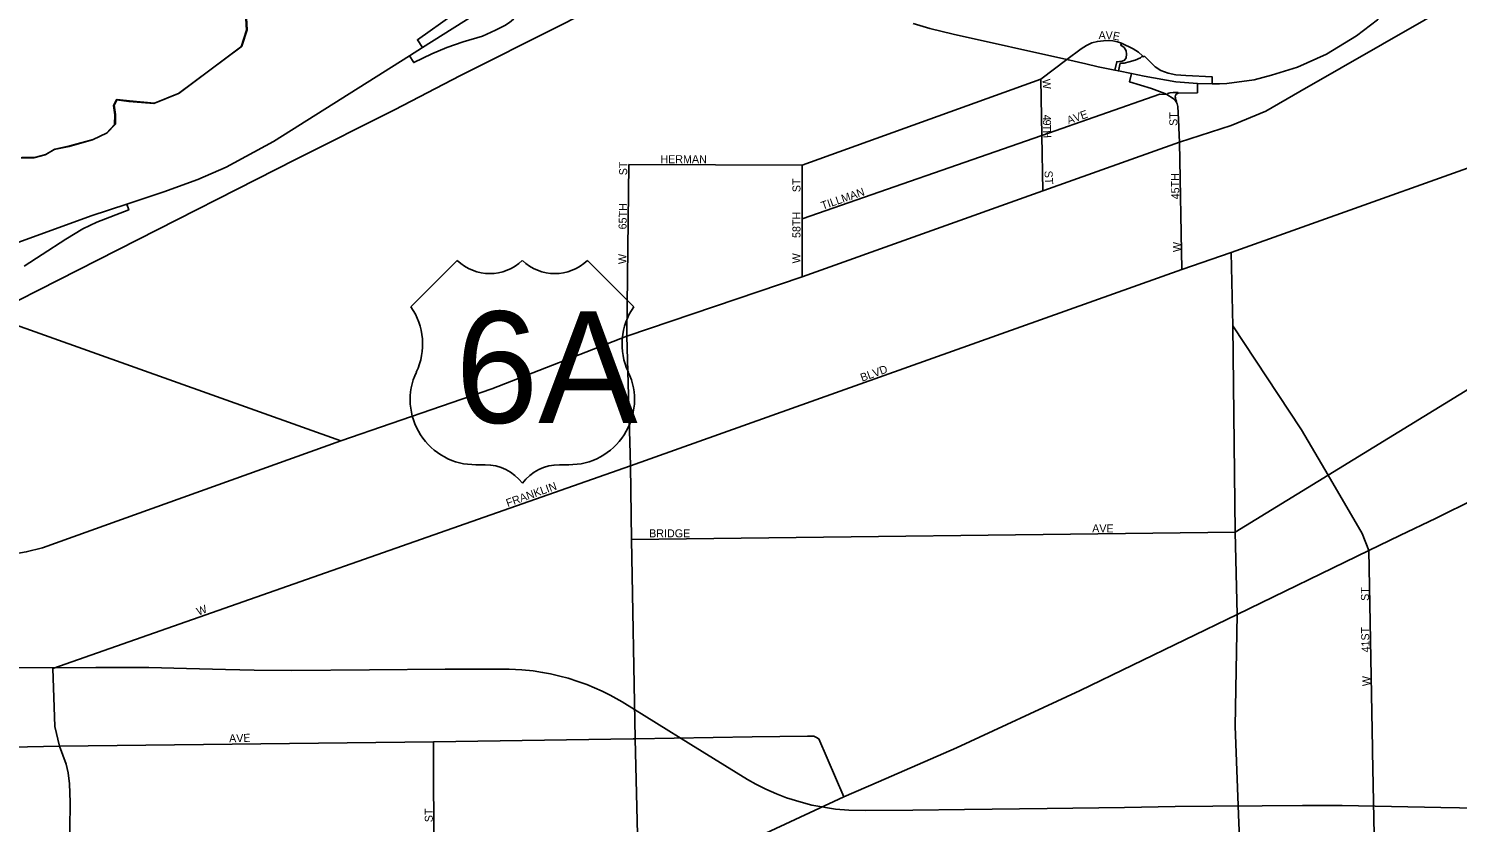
# Model space of a CAD drawing. Extents: x -561 to 1170, y 0 to 846.
# Drawn here: x 204.98 to 229.07, y 265.44 to 278.82 of the extents above; entities that cross this region are included whole.
import ezdxf

# ---------------------------------------------------------------- set-up
doc = ezdxf.new("R2010")
doc.units = 0
for name, color, linetype in [('GM_X_City_Street', 7, 'Continuous'), ('GM_X_City_Street_Text', 7, 'Continuous'), ('GM_X_County', 7, 'Continuous'), ('GM_X_Interchange_Ramps', 7, 'Continuous'), ('GM_X_Major_Lake', 7, 'Continuous'), ('GM_X_Rail_Line', 7, 'Continuous'), ('GM_X_State_Route', 7, 'Continuous'), ('GM_X_US_Location', 7, 'Continuous'), ('GM_X_US_Route', 7, 'Continuous'), ('GM_X_US_Shield', 7, 'Continuous')]:
    doc.layers.add(name, color=color, linetype=linetype)

msp = doc.modelspace()

# ---------------------------------------------------------------- linework, layer by layer
at = {"layer": 'GM_X_City_Street'}
for points in [[(223.779, 278.339), (223.76, 278.361), (223.693, 278.421), (223.604, 278.482), (223.409, 278.575), (223.337, 278.599), (223.262, 278.613), (223.18, 278.618), (223.101, 278.616), (223.002, 278.605), (222.904, 278.58), (222.816, 278.537), (222.728, 278.481), (222.483, 278.301), (222.047, 277.966)], [(222.047, 277.966), (218.021, 276.52), (215.101, 276.529)], [(222.078, 276.083), (222.063, 277.021), (222.047, 277.966)], [(222.063, 277.021), (224.053, 277.714), (224.171, 277.71)], [(224.38, 277.026), (224.367, 277.286), (224.357, 277.51), (224.347, 277.551), (224.329, 277.588), (224.308, 277.619), (224.281, 277.645), (224.171, 277.71)], [(225.254, 275.047), (231.085, 277.124)], [(218.02, 275.613), (222.063, 277.021)], [(224.424, 274.758), (224.386, 276.909), (224.38, 277.026)], [(215.065, 273.687), (215.101, 276.529)], [(218.019, 274.635), (218.02, 275.613), (218.021, 276.52)], [(215.146, 270.207), (225.325, 270.329), (226.891, 271.29), (229.871, 273.119), (233.973, 275.638)], [(224.424, 274.758), (225.254, 275.047)], [(225.391, 263.238), (225.407, 263.396), (225.406, 264.488), (225.406, 264.937), (225.387, 265.424), (225.324, 267.059), (225.36, 268.941), (225.325, 270.329), (225.287, 273.807), (225.254, 275.047)], [(205.386, 268.03), (215.124, 271.45), (224.424, 274.758)], [(202.964, 274.313), (203.134, 274.279), (204.598, 273.883), (210.242, 271.869)], [(226.43, 272.073), (225.287, 273.807)], [(215.264, 253.931), (215.357, 259.417), (215.312, 261.771), (215.265, 264.31), (215.207, 266.848), (215.146, 270.207), (215.124, 271.45), (215.064, 273.633), (215.065, 273.687)], [(227.581, 270.023), (227.466, 270.311), (226.891, 271.29), (226.441, 272.057), (226.43, 272.073)], [(227.641, 266.634), (227.64, 266.687), (227.581, 270.023)], [(205.746, 260.149), (205.705, 260.244), (205.65, 260.443), (205.65, 263.478), (205.678, 265.777), (205.665, 266.089), (205.643, 266.276), (205.612, 266.422), (205.496, 266.721), (205.42, 267.054), (205.386, 268.03)], [(191.454, 266.438), (197.428, 266.555), (205.496, 266.721), (211.806, 266.796), (215.172, 266.847)], [(211.817, 262.781), (211.806, 266.796)], [(215.172, 266.847), (215.207, 266.848), (217.181, 266.878), (218.112, 266.893), (218.218, 266.89), (218.253, 266.873)], [(218.253, 266.873), (218.301, 266.849), (218.724, 265.868)], [(227.739, 261.212), (227.721, 262.466), (227.689, 264.133), (227.68, 264.601), (227.668, 265.222), (227.641, 266.634)]]:
    msp.add_lwpolyline(points, dxfattribs=at)
at = {"layer": 'GM_X_County'}
msp.add_lwpolyline([(204.849, 276.641), (205.066, 276.642), (205.255, 276.692), (205.406, 276.78), (205.66, 276.835), (206.055, 276.946), (206.287, 277.056), (206.427, 277.203), (206.431, 277.365), (206.409, 277.522), (206.457, 277.62), (206.668, 277.594), (207.085, 277.559), (207.501, 277.724), (208.558, 278.515), (208.648, 278.792), (208.624, 279.285)], dxfattribs=at)
at = {"layer": 'GM_X_Interchange_Ramps'}
for points in [[(212.811, 280.059), (212.78, 279.98), (212.674, 279.722), (212.628, 279.622), (212.571, 279.531), (212.482, 279.411), (212.352, 279.268), (212.236, 279.149), (212.137, 279.056), (211.534, 278.634), (211.617, 278.501)], [(211.4, 278.364), (211.471, 278.248), (211.776, 278.396), (212.029, 278.5), (212.305, 278.597), (212.628, 278.696), (212.851, 278.793), (213.006, 278.875), (213.084, 278.923), (213.151, 278.979), (213.267, 279.103), (213.336, 279.199), (213.357, 279.254)], [(223.409, 278.575), (223.394, 278.54), (223.45, 278.502), (223.488, 278.446), (223.492, 278.391), (223.488, 278.327), (223.458, 278.288), (223.42, 278.271), (223.326, 278.263), (223.297, 278.12)], [(223.76, 278.361), (223.727, 278.327), (223.637, 278.288), (223.535, 278.263), (223.454, 278.237), (223.382, 278.237), (223.355, 278.108)], [(224.936, 277.889), (224.938, 278.007), (224.49, 278.032), (224.324, 278.041), (224.196, 278.071), (224.072, 278.113), (223.974, 278.177), (223.797, 278.354), (223.779, 278.339)], [(223.575, 278.063), (223.544, 277.921), (223.914, 277.809), (224.094, 277.745), (224.139, 277.725), (224.171, 277.71)], [(224.329, 277.588), (224.337, 277.593), (224.324, 277.619), (224.315, 277.653), (224.313, 277.671), (224.316, 277.692), (224.329, 277.714), (224.35, 277.727), (224.362, 277.731), (224.687, 277.738), (224.69, 277.893)], [(224.171, 277.71), (224.19, 277.726), (224.206, 277.734), (224.226, 277.738), (224.278, 277.741), (224.362, 277.742), (224.362, 277.731)], [(204.902, 274.818), (205.207, 275.012), (205.601, 275.272), (205.891, 275.443), (206.129, 275.555), (206.664, 275.763), (206.631, 275.861)]]:
    msp.add_lwpolyline(points, dxfattribs=at)
at = {"layer": 'GM_X_Major_Lake'}
msp.add_lwpolyline([(204.861, 276.648), (205.077, 276.649), (205.267, 276.699), (205.418, 276.787), (205.672, 276.842), (206.067, 276.953), (206.299, 277.063), (206.439, 277.21), (206.443, 277.372), (206.42, 277.529), (206.469, 277.627), (206.68, 277.601), (207.097, 277.566), (207.513, 277.731), (208.57, 278.522), (208.66, 278.799), (208.635, 279.292)], dxfattribs=at)
at = {"layer": 'GM_X_Rail_Line'}
for points in [[(197.077, 270.293), (200.273, 271.928), (203.47, 273.56), (209.487, 276.62), (211.146, 277.453), (212.262, 278.028), (213.918, 278.864), (215.28, 279.559), (215.714, 279.774), (217.261, 280.569), (217.693, 280.79), (218.131, 281.017), (218.428, 281.186), (218.73, 281.358), (219.028, 281.542), (219.677, 281.985), (220.829, 282.791), (222.601, 284.04), (224.719, 285.505)], [(204.621, 268.042), (206.109, 268.052), (207.001, 268.048), (207.639, 268.034), (208.296, 268.015), (208.782, 268.005), (209.417, 268), (210.724, 268.011), (211.999, 268.022), (213.078, 268.022), (213.292, 268.013), (213.486, 267.993), (213.645, 267.966), (213.78, 267.941), (213.932, 267.904), (214.073, 267.869), (214.237, 267.816), (214.388, 267.762), (214.522, 267.707), (214.647, 267.65), (214.785, 267.582), (214.984, 267.469), (216.144, 266.749), (217.098, 266.164), (217.241, 266.085), (217.409, 265.998), (217.59, 265.92), (217.759, 265.853), (218.002, 265.777), (218.187, 265.731)], [(218.187, 265.731), (218.586, 265.663), (218.809, 265.645), (219.082, 265.639), (219.888, 265.645), (220.76, 265.653), (222.156, 265.673), (223.459, 265.688), (224.313, 265.705), (224.945, 265.711), (225.782, 265.719), (226.457, 265.725), (227.127, 265.722), (228.793, 265.688), (229.737, 265.67)]]:
    msp.add_lwpolyline(points, dxfattribs=at)
at = {"layer": 'GM_X_State_Route'}
for points in [[(219.308, 266.123), (220.622, 266.696), (222.711, 267.664), (225.36, 268.941), (227.581, 270.023), (228.102, 270.274), (228.711, 270.57), (229.373, 270.892), (230.356, 271.362), (230.602, 271.478), (231.174, 271.751), (231.804, 272.052), (232.359, 272.331), (232.843, 272.579), (233.092, 272.697), (233.394, 272.883), (233.645, 273.045), (234.315, 273.462), (235.012, 273.892)], [(207.911, 260.99), (207.941, 261.004), (209.132, 261.538), (211.647, 262.696), (211.817, 262.781), (215.265, 264.31), (215.836, 264.564), (216.586, 264.876), (218.724, 265.868), (219.308, 266.123)]]:
    msp.add_lwpolyline(points, dxfattribs=at)
at = {"layer": 'GM_X_US_Route'}
for points in [[(225.057, 277.892), (225.183, 277.895), (225.642, 277.958), (225.934, 278.034), (226.376, 278.169), (226.864, 278.391), (227.369, 278.698), (227.724, 278.967), (227.961, 279.211), (228.181, 279.445), (228.397, 279.656)], [(204.565, 275.13), (206.031, 275.662), (206.631, 275.861), (207.254, 276.068), (207.832, 276.277), (208.308, 276.482), (209.104, 276.916), (211.4, 278.364), (211.617, 278.501), (213.211, 279.506)], [(222.099, 276.091), (224.386, 276.909), (225.255, 277.189), (225.84, 277.429), (226.412, 277.763), (229.201, 279.362), (229.299, 279.418)], [(219.894, 278.907), (220.177, 278.82), (220.569, 278.726), (222.483, 278.301), (222.808, 278.225)], [(222.808, 278.225), (223.015, 278.177), (223.297, 278.12), (223.355, 278.108), (223.575, 278.063), (223.788, 278.02), (224.324, 277.922), (224.69, 277.893), (224.936, 277.889), (225.057, 277.892)], [(210.242, 271.869), (212.786, 272.747), (215.064, 273.633), (218.019, 274.635), (222.078, 276.083), (222.099, 276.091)], [(200.373, 269.475), (200.373, 269.475), (204.715, 269.959), (204.935, 269.997), (205.21, 270.066), (210.242, 271.869)]]:
    msp.add_lwpolyline(points, dxfattribs=at)
at = {"layer": 'GM_X_US_Shield'}
for p, q in [((212.206, 274.914), (211.423, 274.131)), ((215.182, 274.131), (214.399, 274.914)), ((212.519, 271.468), (212.676, 271.468)), ((213.929, 271.468), (214.085, 271.468))]:
    msp.add_line(p, q, dxfattribs=at)
for centre, radius, start, end in [((212.754, 275.473), 0.783, 225.573, 314.427), ((213.851, 275.473), 0.783, 225.573, 314.427), ((210.525, 273.502), 1.096, 334.5471, 35.0009), ((216.08, 273.502), 1.096, 144.9991, 205.4529), ((212.507, 272.564), 1.096, 154.8319, 270.6383), ((214.098, 272.564), 1.096, 269.3617, 25.1681), ((212.676, 270.685), 0.783, 36.8699, 90), ((213.929, 270.685), 0.783, 90, 143.1301)]:
    msp.add_arc(centre, radius, start, end, dxfattribs=at)

# ---------------------------------------------------------------- texts
at = {"layer": 'GM_X_City_Street_Text'}
for s, rotation, p in [('A', 359.5191, (223.02, 278.643)), ('V', 359.1038, (223.138, 278.642)), ('E', 349.0598, (223.251, 278.64)), ('W', 274.7606, (222.071, 277.966)), ('4', 270.0625, (222.083, 277.37)), ('AVE', 19.6509, (222.513, 277.204)), ('ST', 90, (224.349, 277.18)), ('9', 270.0312, (222.083, 277.287)), ('T', 270.0668, (222.083, 277.203)), ('H', 271.625, (222.084, 277.104)), ('HERMAN', 0, (215.631, 276.552)), ('ST', 90, (215.071, 276.348)), ('ST', 273.5882, (222.107, 276.421)), ('ST', 90, (217.993, 276.063)), ('45TH', 91.3684, (224.385, 275.944)), ('TILLMAN', 19.0253, (218.367, 275.766)), ('65TH', 88.6369, (215.059, 275.434)), ('58TH', 90, (217.993, 275.291)), ('W', 90, (224.409, 275.053)), ('W', 90, (215.059, 274.851)), ('W', 90, (217.993, 274.863)), ('BLVD', 19.8563, (219.032, 272.867)), ('FRANKLIN', 19.799, (213.056, 270.753)), ('BRIDGE', 0, (215.441, 270.244)), ('AVE', 0, (222.913, 270.327)), ('ST', 90, (227.58, 269.173)), ('W', 21.0409, (207.84, 268.923)), ('41ST', 91.4313, (227.592, 268.305)), ('W', 90, (227.604, 267.735)), ('AVE', 1.9814, (208.359, 266.786)), ('ST', 90, (211.792, 265.442))]:
    msp.add_text(s, height=0.135, rotation=rotation, dxfattribs=at).set_placement(p)
at = {"layer": 'GM_X_US_Location'}
for s in ['/', '0']:
    msp.add_text(s, height=0.0027, dxfattribs=at).set_placement((213.301, 273.098))
msp.add_text('6A', height=0.0027, rotation=0, dxfattribs=at).set_placement((212.661, 272.539))
at = {"layer": 'GM_X_US_Shield'}
msp.add_text('6A', height=1.8795, dxfattribs=at).set_placement((212.173, 272.173))

doc.saveas('drawing.dxf')
